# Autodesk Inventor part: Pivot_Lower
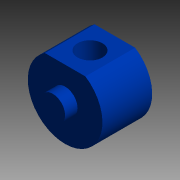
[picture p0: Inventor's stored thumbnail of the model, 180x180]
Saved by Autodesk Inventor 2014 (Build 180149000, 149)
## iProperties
Shininess: 0.0
Length Units: 11272
Angle Units: 11279
Time Units: 11290
Mass Units: 11283
Length Display Precision: 2
Angle Display Precision: 1
Compacted: True
Created: 1999-05
Part Number: Pivot_Lower
Document SubType Name: Modeling
Designer: Administrator
Density: 7.85 g/cm^3
Material: Steel
Mass: 22.7912 g
Surface Area: 17.5632 cm^2
Volume: 2.90333 cm^3
Appearance: Blue - Semi Gloss
Density: 0.0
Volumn: 0.0
Area: 0.0
PropertySet Name: Model Information
Control State: 0
Master: False
Checked Out: False
Author: Administrator
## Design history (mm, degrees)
node "y-z Plane"
  node "x-z Plane"
  node "x-y Plane"
node "Extrusion1" dims "d1" = 12.7, "d2" = 0
  sketch "Sketch1"
    geometry: C1 r 9.525 at (0, 0); 1 further point
    constraints: 1 centre point, 1 coincident
    dimensions: "d0" = 19.05 diameter of C1
node "Extrusion2" dims "d4" = 19.05, "d5" = 0
  sketch "Sketch2"
    geometry: L1 (-5.168, 8.001)-(5.168, 8.001); A1 r 9.525 centre (0, 0) between (-5.168, 8.001) and (5.168, 8.001) reference
    constraints: 2 end point, 2 point on circle, 1 horizontal
    dimensions: "d3" = 17.526 dimension on A1 L1
node "Extrusion3" dims "d7" = 3.175, "d8" = 0
  sketch "Sketch3"
    geometry: C1 r 3.175 at (0, 0); A1 r 9.525 centre (0, 0) between (-5.168, 8.001) and (5.168, 8.001) reference
    constraints: 1 centre point
    dimensions: "d6" = 6.35 diameter of C1
node "Extrusion4" dims "d10" = 3.175, "d11" = 0
  sketch "Sketch4"
    geometry: C1 r 3.175 at (0, 0); A1 r 9.525 centre (0, 0) between (-5.168, 8.001) and (5.168, 8.001) reference
    constraints: 1 centre point
    dimensions: "d9" = 6.34968 diameter of C1
workplane "Work Plane1"
node "Hole1" dims "d14" = 6.35, "d15" = 9.525, "d16" = 6.35, "d17" = 60 deg, "d18" = 19.05, "d19" = 118 deg
  sketch "Sketch5"
    geometry: 2 further points
    constraints: 1 coincident
body "Solid1"
